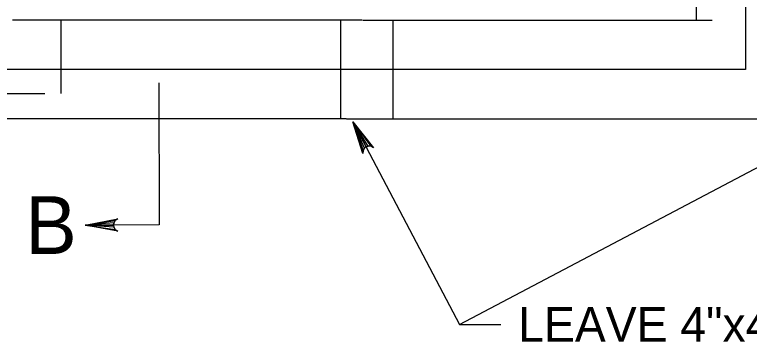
# Model space of a CAD drawing. Extents: x 2.4 to 9.7, y 1.1 to 11.2.
# Drawn here: x 7.421 to 8.695, y 4.808 to 5.375 of the extents above; entities that cross this region are included whole.
import ezdxf

# ---------------------------------------------------------------- set-up
doc = ezdxf.new("R2010")
doc.units = 0
for name, color, linetype in [('DETL-DIMS', 7, 'Continuous'), ('DETL-LINE', 7, 'Continuous'), ('DETL-NOTE', 7, 'Continuous'), ('DETL-TITL', 7, 'Continuous')]:
    doc.layers.add(name, color=color, linetype=linetype)

msp = doc.modelspace()

# ---------------------------------------------------------------- linework, layer by layer
at = {"layer": 'DETL-DIMS'}
for p, q in [((8.1921, 4.8386), (9.0734, 5.3027)), ((7.6706, 5.2569), (7.6712, 5.0109)), ((8.0073, 5.1895), (8.1921, 4.8386)), ((7.6712, 5.0109), (7.5431, 5.0106)), ((8.1921, 4.8386), (8.2637, 4.8386))]:
    msp.add_line(p, q, dxfattribs=at)
for points in [[(8.0073, 5.1895), (8.043, 5.1444), (8.0383, 5.1469), (8.0339, 5.1471), (8.0303, 5.1459), (8.0272, 5.1436), (8.0249, 5.1398), (8.0243, 5.1346), (8.0073, 5.1895), (8.0249, 5.1398), (8.0272, 5.1436), (8.0073, 5.1895), (8.0303, 5.1459), (8.0339, 5.1471), (8.0073, 5.1895), (8.0383, 5.1469)], [(7.5431, 5.0106), (7.5996, 5.0213), (7.5952, 5.0183), (7.593, 5.0145), (7.5923, 5.0107), (7.593, 5.0069), (7.5953, 5.0032), (7.5996, 5.0002), (7.5431, 5.0106), (7.5953, 5.0032), (7.593, 5.0069), (7.5431, 5.0106), (7.5923, 5.0107), (7.593, 5.0145), (7.5431, 5.0106), (7.5952, 5.0183)]]:
    msp.add_lwpolyline(points, dxfattribs=at)
at = {"layer": 'DETL-LINE'}
for p, q in [((8.6877, 6.5054), (8.6877, 5.2799)), ((8.6025, 6.4562), (8.6025, 5.3652)), ((8.0233, 5.3652), (7.4172, 5.3652)), ((7.5013, 5.2385), (7.5013, 5.3652)), ((7.9862, 5.1947), (7.9862, 5.3652)), ((8.0243, 5.3652), (8.6304, 5.3652)), ((8.0771, 5.1947), (8.0771, 5.3652)), ((8.6877, 5.2799), (6.091, 5.2799)), ((7.3053, 5.2385), (7.4734, 5.2385)), ((7.9954, 5.1947), (7.2189, 5.1947)), ((7.9964, 5.1947), (8.7729, 5.1947))]:
    msp.add_line(p, q, dxfattribs=at)

# ---------------------------------------------------------------- texts
at = {"layer": 'DETL-NOTE'}
msp.add_text('LEAVE 4"x4" OPENING FOR', height=0.06, dxfattribs=at).set_placement((8.294, 4.8086))
at = {"layer": 'DETL-TITL'}
msp.add_text('B', height=0.1, dxfattribs=at).set_placement((7.4393, 4.9606))

doc.saveas('drawing.dxf')
